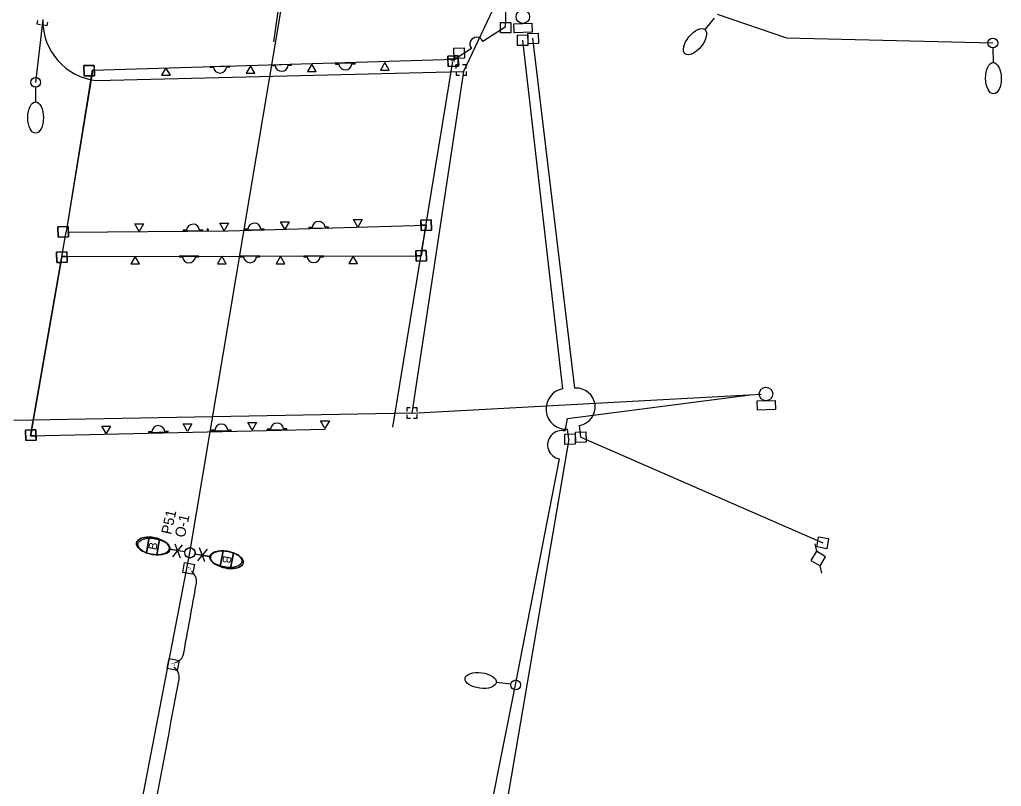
# Model space of a CAD drawing. Extents: x 925407 to 930994, y 604905 to 637063.
# Drawn here: x 930469.3 to 930944.1, y 618416 to 618786.5 of the extents above; entities that cross this region are included whole.
import ezdxf

# ---------------------------------------------------------------- set-up
doc = ezdxf.new("R2010")
doc.units = 0
for name, color, linetype in [('ActivePointCell_dp', 7, 'Continuous'), ('Conduit', 7, 'Continuous'), ('ConduitDB', 7, 'Continuous'), ('ConduitJB', 7, 'Continuous'), ('ConduitOT', 7, 'Continuous'), ('LightingMisc', 7, 'Continuous'), ('LiteCond_ep', 7, 'Continuous'), ('LoadCenter', 7, 'Continuous'), ('LoadCenter_ep', 7, 'Continuous'), ('Miscellaneous2', 7, 'Continuous'), ('Miscellaneous9', 7, 'Continuous'), ('PoleElec_ep', 7, 'Continuous'), ('PoleLight', 7, 'Continuous'), ('PoleLight_ep', 7, 'Continuous'), ('PullBox', 7, 'Continuous'), ('SoilBoxes_px', 7, 'Continuous')]:
    doc.layers.add(name, color=color, linetype=linetype)

msp = doc.modelspace()

# ---------------------------------------------------------------- linework, layer by layer
for points in [[(930560.46, 618685.29), (930560.02, 618685.33), (930559.93, 618684.52), (930560.37, 618684.47)], [(930560.37, 618684.47), (930560.46, 618685.29), (930560.46, 618685.29), (930560.37, 618684.47)]]:
    msp.add_lwpolyline(points, close=True)
at = {"layer": 'ActivePointCell_dp'}
msp.add_line((930618.39, 618963.87), (930592.1, 618775.67), dxfattribs=at)
at = {"layer": 'Conduit'}
for p, q in [((930720.15, 618838.16), (930683.96, 618761.37)), ((930806.63, 618789.06), (930840.21, 618777.66)), ((930480.53, 618786.47), (930477.05, 618756.15)), ((930840.21, 618777.66), (930939.95, 618775.21)), ((930506.57, 618757.04), (930683.96, 618761.37)), ((930683.96, 618761.37), (930659.01, 618596.36)), ((930659.01, 618596.36), (930827.84, 618605.52)), ((930734.26, 618593.79), (930822.57, 618605.19)), ((930659.01, 618596.36), (930466.5, 618592.68)), ((930733.07, 618587.68), (930734.26, 618593.79)), ((930709.17, 618464.99), (930730.45, 618574.22)), ((930671.82, 618277.75), (930709.17, 618464.96))]:
    msp.add_line(p, q, dxfattribs=at)
for centre, radius, start, end in [((930509.6, 618785.96), 29.08, 178.9945, 264.0152), ((930731.51, 618581), 6.87, 76.85, 261.1041)]:
    msp.add_arc(centre, radius, start, end, dxfattribs=at)
at = {"layer": 'ConduitDB'}
for p, q in [((930732.07, 618608.04), (930712.58, 618776.48)), ((930737.86, 618608.37), (930717.5, 618777.55)), ((930740.7, 618584.75), (930740.03, 618590.39)), ((930734.88, 618583.7), (930734.32, 618588.54)), ((930740.7, 618584.75), (930857.66, 618533.69))]:
    msp.add_line(p, q, dxfattribs=at)
for centre, radius, start, end in [((930733.68, 618598.35), 9.83, 99.4413, 273.7548), ((930738.6, 618599.34), 9.06, 279.0871, 94.6401)]:
    msp.add_arc(centre, radius, start, end, dxfattribs=at)
at = {"layer": 'ConduitJB'}
for p, q in [((930504.59, 618762.1), (930679.89, 618767.39)), ((930679.64, 618767.67), (930680.88, 618767.71)), ((930492.01, 618683.91), (930504.59, 618762.1)), ((930492.54, 618683.83), (930570.06, 618684.49)), ((930570.13, 618684.45), (930665.97, 618687.21)), ((930663.56, 618672.32), (930665.97, 618687.21)), ((930489.8, 618672), (930474.65, 618585.35)), ((930489.8, 618672), (930663.56, 618672.32)), ((930474.65, 618585.35), (930617, 618588.64))]:
    msp.add_line(p, q, dxfattribs=at)
at = {"layer": 'ConduitOT'}
for p, q in [((930704.72, 618801.33), (930704.15, 618782.79)), ((930704.15, 618782.79), (930693.37, 618775.96)), ((930687.86, 618772.46), (930679.94, 618767.43))]:
    msp.add_line(p, q, dxfattribs=at)
msp.add_lwpolyline([(930734.88, 618583.7), (930694.71, 618348.94)], dxfattribs=at)
for centre, radius, start, end in [((930690.34, 618774.64), 3.3, 23.4064, 221.404), ((930549.39, 618515.13), 5.5, 349.5299, 57.2394), ((919236.07, 620547.92), 11500, 349.639964, 349.813549), ((930543.25, 618481.17), 5.5, 281.9557, 349.5925), ((930540.98, 618468.82), 5.5, 349.5299, 57.2394), ((919236.07, 620547.92), 11500, 348.486539, 349.579184)]:
    msp.add_arc(centre, radius, start, end, dxfattribs=at)
at = {"layer": 'LightingMisc'}
for p, q in [((930600.75, 618764.81), (930591.23, 618764.54)), ((930591.23, 618764.54), (930591.24, 618764.22)), ((930599.15, 618764.44), (930600.76, 618764.49)), ((930600.76, 618764.49), (930600.75, 618764.81)), ((930631.62, 618765.42), (930622.1, 618765.25)), ((930622.1, 618765.25), (930622.1, 618764.93)), ((930622.1, 618764.93), (930623.71, 618764.96)), ((930630.02, 618765.07), (930631.62, 618765.1)), ((930631.62, 618765.1), (930631.62, 618765.42)), ((930570.94, 618763.93), (930561.42, 618763.72)), ((930561.42, 618763.72), (930561.43, 618763.41)), ((930561.43, 618763.41), (930563.03, 618763.44)), ((930569.34, 618763.58), (930570.95, 618763.62)), ((930570.95, 618763.62), (930570.94, 618763.93)), ((930591.24, 618764.22), (930592.84, 618764.27)), ((930550.03, 618684.73), (930548.43, 618684.72)), ((930548.43, 618684.72), (930548.43, 618684.4)), ((930548.43, 618684.4), (930557.95, 618684.48)), ((930557.95, 618684.8), (930556.35, 618684.79)), ((930557.95, 618684.48), (930557.95, 618684.8)), ((930579.69, 618685.21), (930578.09, 618685.19)), ((930578.09, 618685.19), (930578.09, 618684.87)), ((930578.09, 618684.87), (930587.61, 618684.96)), ((930587.61, 618685.27), (930586.01, 618685.26)), ((930587.61, 618684.96), (930587.61, 618685.27)), ((930610.71, 618686.06), (930609.11, 618686.05)), ((930609.11, 618686.05), (930609.11, 618685.73)), ((930609.11, 618685.73), (930618.63, 618685.81)), ((930618.63, 618686.13), (930617.03, 618686.12)), ((930618.63, 618685.81), (930618.63, 618686.13)), ((930555.92, 618672.12), (930546.4, 618672.11)), ((930546.4, 618672.11), (930546.4, 618671.79)), ((930546.4, 618671.79), (930548, 618671.79)), ((930554.32, 618671.8), (930555.92, 618671.81)), ((930555.92, 618671.81), (930555.92, 618672.12)), ((930585.51, 618672.18), (930575.99, 618672.16)), ((930575.99, 618672.16), (930575.99, 618671.85)), ((930575.99, 618671.85), (930577.6, 618671.85)), ((930583.91, 618671.86), (930585.51, 618671.86)), ((930585.51, 618671.86), (930585.51, 618672.18)), ((930616.28, 618672.23), (930606.76, 618672.22)), ((930606.76, 618672.22), (930606.76, 618671.9)), ((930606.76, 618671.9), (930608.36, 618671.9)), ((930614.68, 618671.91), (930616.28, 618671.92)), ((930616.28, 618671.92), (930616.28, 618672.23)), ((930598.6, 618588.79), (930597, 618588.75)), ((930598.61, 618588.47), (930598.6, 618588.79)), ((930533.19, 618587.35), (930531.58, 618587.31)), ((930531.58, 618587.31), (930531.59, 618586.99)), ((930531.59, 618586.99), (930541.11, 618587.21)), ((930541.1, 618587.53), (930539.5, 618587.49)), ((930541.11, 618587.21), (930541.1, 618587.53)), ((930563.7, 618588.11), (930562.1, 618588.1)), ((930562.1, 618588.1), (930562.1, 618587.78)), ((930562.1, 618587.78), (930571.62, 618587.84)), ((930571.62, 618588.15), (930570.01, 618588.14)), ((930571.62, 618587.84), (930571.62, 618588.15)), ((930590.69, 618588.62), (930589.08, 618588.58)), ((930589.08, 618588.58), (930589.09, 618588.26)), ((930589.09, 618588.26), (930598.61, 618588.47))]:
    msp.add_line(p, q, dxfattribs=at)
for points in [[(930608.56, 618761.33), (930612.78, 618761.33), (930610.67, 618764.99)], [(930643.82, 618762.06), (930648.04, 618762.06), (930645.93, 618765.72)], [(930537.99, 618759.56), (930542.21, 618759.56), (930540.1, 618763.21)], [(930578.83, 618760.56), (930583.05, 618760.56), (930580.94, 618764.22)], [(930595.47, 618688.84), (930599.68, 618688.84), (930597.58, 618685.19)], [(930630.77, 618689.86), (930634.99, 618689.86), (930632.88, 618686.2)], [(930525, 618687.72), (930529.22, 618687.72), (930527.11, 618684.07)], [(930566.09, 618688.07), (930570.31, 618688.07), (930568.2, 618684.42)], [(930523.08, 618668.42), (930527.3, 618668.42), (930525.19, 618672.08)], [(930564.97, 618668.54), (930569.19, 618668.54), (930567.08, 618672.19)], [(930593.38, 618668.52), (930597.6, 618668.52), (930595.49, 618672.17)], [(930628.53, 618668.58), (930632.75, 618668.58), (930630.64, 618672.24)], [(930509.05, 618590.08), (930513.27, 618590.08), (930511.16, 618586.43)], [(930548.44, 618591.08), (930552.66, 618591.08), (930550.55, 618587.42)], [(930579.61, 618591.75), (930583.83, 618591.75), (930581.72, 618588.09)], [(930614.88, 618592.56), (930619.1, 618592.56), (930616.99, 618588.91)]]:
    msp.add_lwpolyline(points, close=True, dxfattribs=at)
for centre, start, end in [((930595.99, 618764.67), 187.3392, 355.8608), ((930626.86, 618765.33), 186.7733, 355.2948), ((930566.18, 618763.83), 186.9974, 355.519), ((930613.87, 618685.77), 6.2311, 174.7527), ((930553.19, 618684.44), 6.2264, 174.748), ((930582.85, 618684.92), 6.2264, 174.748), ((930551.16, 618672.12), 185.8184, 354.34), ((930580.75, 618672.17), 185.8184, 354.34), ((930611.52, 618672.23), 185.8184, 354.34), ((930536.35, 618587.1), 7.061, 175.5826), ((930566.86, 618587.81), 6.0485, 174.5701), ((930593.85, 618588.37), 6.9778, 175.4994)]:
    msp.add_arc(centre, 3.17, start, end, dxfattribs=at)
at = {"layer": 'LiteCond_ep'}
for p, q in [((930551.66, 618528.87), (930598.48, 618807.43)), ((930505.44, 618764.38), (930500.44, 618764.25)), ((930505.5, 618762.12), (930505.44, 618764.38)), ((930679.57, 618768.98), (930676.35, 618768.9)), ((930676.35, 618768.9), (930676.39, 618767.29)), ((930676.39, 618767.29), (930679.48, 618767.38)), ((930676.39, 618767.29), (930676.48, 618763.9)), ((930679.64, 618767.67), (930679.48, 618767.38)), ((930679.48, 618767.38), (930679.65, 618767.39)), ((930679.48, 618767.38), (930679.89, 618767.39)), ((930681.35, 618769.02), (930679.57, 618768.98)), ((930681.35, 618769.02), (930679.57, 618768.98)), ((930679.64, 618767.67), (930679.57, 618768.98)), ((930679.57, 618768.98), (930679.64, 618767.67)), ((930679.83, 618767.71), (930679.57, 618768.98)), ((930679.83, 618767.68), (930679.64, 618767.67)), ((930679.64, 618767.67), (930679.83, 618767.68)), ((930679.83, 618767.68), (930679.83, 618767.71)), ((930679.84, 618767.66), (930679.83, 618767.68)), ((930680.33, 618767.67), (930679.84, 618767.66)), ((930680.8, 618767.68), (930679.89, 618767.39)), ((930679.89, 618767.39), (930680.33, 618767.67)), ((930680.33, 618767.67), (930679.89, 618767.39)), ((930679.89, 618767.39), (930680.37, 618767.55)), ((930680.3, 618764.61), (930681.46, 618764.62)), ((930681.46, 618764.62), (930680.3, 618764.61)), ((930680.3, 618764), (930680.3, 618764.61)), ((930680.3, 618764.61), (930680.3, 618764)), ((930680.72, 618767.7), (930680.33, 618767.67)), ((930680.33, 618767.67), (930680.72, 618767.7)), ((930680.36, 618767.69), (930680.33, 618767.67)), ((930680.73, 618767.93), (930680.36, 618767.69)), ((930680.73, 618767.93), (930680.36, 618767.69)), ((930680.36, 618767.69), (930680.88, 618767.71)), ((930680.88, 618767.71), (930680.36, 618767.69)), ((930680.36, 618767.69), (930680.72, 618767.7)), ((930680.72, 618767.7), (930680.36, 618767.69)), ((930680.36, 618767.69), (930680.72, 618767.7)), ((930680.36, 618767.69), (930680.36, 618767.69)), ((930680.37, 618767.55), (930680.8, 618767.68)), ((930680.72, 618767.7), (930680.88, 618767.71)), ((930680.72, 618767.7), (930680.85, 618767.71)), ((930680.85, 618767.71), (930680.72, 618767.7)), ((930680.8, 618767.7), (930680.72, 618767.7)), ((930681.37, 618768.33), (930680.73, 618767.93)), ((930681.37, 618768.33), (930680.73, 618767.93)), ((930680.8, 618767.68), (930681.39, 618767.7)), ((930680.85, 618767.7), (930680.8, 618767.68)), ((930680.8, 618767.68), (930680.85, 618767.7)), ((930680.85, 618767.7), (930680.8, 618767.7)), ((930680.85, 618767.71), (930680.88, 618767.71)), ((930680.88, 618767.71), (930681.06, 618767.7)), ((930680.88, 618767.71), (930681.06, 618767.7)), ((930681.06, 618767.7), (930681.38, 618767.71)), ((930681.39, 618767.7), (930681.06, 618767.7)), ((930681.06, 618767.7), (930681.39, 618767.7)), ((930681.37, 618768.33), (930681.35, 618769.02)), ((930681.37, 618768.33), (930681.35, 618769.02)), ((930681.38, 618767.71), (930681.37, 618768.33)), ((930681.39, 618767.7), (930681.37, 618768.33)), ((930681.46, 618764.62), (930681.39, 618767.7)), ((930681.48, 618764.1), (930681.46, 618764.62)), ((930500.44, 618764.25), (930500.57, 618759.25)), ((930504.15, 618759.34), (930504.59, 618762.1)), ((930504.59, 618762.1), (930504.15, 618759.34)), ((930504.59, 618762.1), (930505.5, 618762.12)), ((930505.5, 618762.12), (930504.59, 618762.1)), ((930505.57, 618759.38), (930505.5, 618762.12)), ((930676.48, 618763.9), (930680.3, 618764)), ((930680.3, 618764), (930681.41, 618764.02)), ((930500.57, 618759.25), (930504.15, 618759.34)), ((930504.15, 618759.34), (930505.57, 618759.38)), ((930668.4, 618689.77), (930663.4, 618689.64)), ((930663.4, 618689.64), (930663.47, 618687.14)), ((930668.53, 618684.77), (930668.4, 618689.77)), ((930487.84, 618686.33), (930487.97, 618681.33)), ((930665.97, 618687.21), (930663.47, 618687.14)), ((930663.47, 618687.14), (930665.97, 618687.21)), ((930663.47, 618687.14), (930663.53, 618684.65)), ((930663.53, 618684.65), (930665.56, 618684.7)), ((930665.56, 618684.7), (930665.97, 618687.21)), ((930665.97, 618687.21), (930665.56, 618684.7)), ((930665.56, 618684.7), (930668.53, 618684.77)), ((930487.97, 618681.33), (930492.97, 618681.46)), ((930492.18, 618674.25), (930487.18, 618674.12)), ((930487.18, 618674.12), (930487.31, 618669.13)), ((930492.24, 618672.01), (930492.18, 618674.25)), ((930663.96, 618674.84), (930660.99, 618674.76)), ((930660.99, 618674.76), (930661.06, 618672.32)), ((930663.96, 618674.84), (930663.56, 618672.32)), ((930663.56, 618672.32), (930663.96, 618674.84)), ((930665.99, 618674.89), (930663.96, 618674.84)), ((930666.12, 618669.89), (930665.99, 618674.89)), ((930489.31, 618669.18), (930489.8, 618672)), ((930489.8, 618672), (930489.31, 618669.18)), ((930489.8, 618672), (930492.24, 618672.01)), ((930492.24, 618672.01), (930489.8, 618672)), ((930492.31, 618669.25), (930492.24, 618672.01)), ((930663.56, 618672.32), (930661.06, 618672.32)), ((930661.06, 618672.32), (930661.12, 618669.76)), ((930661.06, 618672.32), (930663.56, 618672.32)), ((930661.12, 618669.76), (930666.12, 618669.89)), ((930487.31, 618669.13), (930489.31, 618669.18)), ((930489.31, 618669.18), (930492.31, 618669.25)), ((930475.15, 618588.19), (930472.14, 618588.11)), ((930472.14, 618588.11), (930472.27, 618583.11)), ((930474.65, 618585.35), (930475.15, 618588.19)), ((930475.15, 618588.19), (930474.65, 618585.35)), ((930477.21, 618585.41), (930474.65, 618585.35)), ((930474.65, 618585.35), (930477.21, 618585.41)), ((930477.14, 618588.24), (930475.15, 618588.19)), ((930477.21, 618585.41), (930477.14, 618588.24)), ((930477.27, 618583.24), (930477.21, 618585.41)), ((930472.27, 618583.11), (930477.27, 618583.24)), ((930498.32, 618253.03), (930551.66, 618528.87))]:
    msp.add_line(p, q, dxfattribs=at)
for points in [[(930679.89, 618767.39), (930679.48, 618767.38), (930676.39, 618767.29)], [(930679.57, 618768.98), (930679.82, 618767.72), (930679.84, 618767.66)], [(930679.57, 618768.98), (930679.83, 618767.71), (930679.83, 618767.68)], [(930679.64, 618767.67), (930679.83, 618767.71)], [(930679.83, 618767.71), (930679.64, 618767.67)], [(930679.65, 618767.39), (930679.64, 618767.67)], [(930679.83, 618767.68), (930679.84, 618767.68), (930680.33, 618767.69), (930680.36, 618767.69)], [(930679.84, 618767.66), (930679.89, 618767.66), (930680.33, 618767.67)], [(930680.33, 618767.67), (930680.73, 618767.93), (930681.37, 618768.33)], [(930680.37, 618767.55), (930680.33, 618767.67)], [(930680.33, 618767.67), (930680.37, 618767.55)], [(930680.36, 618767.69), (930680.73, 618767.93), (930681.37, 618768.33)], [(930680.72, 618767.7), (930680.8, 618767.7), (930680.85, 618767.7)], [(930681.39, 618767.7), (930680.88, 618767.69), (930680.8, 618767.68)], [(930680.8, 618767.68), (930680.8, 618767.7)], [(930680.8, 618767.7), (930680.8, 618767.68)], [(930680.85, 618767.7), (930680.85, 618767.71)], [(930681.06, 618767.7), (930680.88, 618767.7), (930680.85, 618767.7)], [(930681.41, 618764.02), (930681.44, 618764.06), (930681.48, 618764.1)], [(930492.84, 618686.46), (930492.42, 618686.45), (930487.84, 618686.33)], [(930492.97, 618681.46), (930492.91, 618683.83), (930492.84, 618686.46)]]:
    msp.add_lwpolyline(points, dxfattribs=at)
at = {"layer": 'LoadCenter'}
for p, q in [((930708.36, 618784.5), (930717.09, 618784.73)), ((930708.47, 618780.14), (930708.36, 618784.5)), ((930717.09, 618784.73), (930717.2, 618780.36)), ((930717.2, 618780.36), (930708.47, 618780.14))]:
    msp.add_line(p, q, dxfattribs=at)
msp.add_circle((930712.64, 618787.89), 3.27, dxfattribs=at)
at = {"layer": 'LoadCenter_ep'}
for p, q in [((930825.97, 618602.19), (930834.69, 618602.42)), ((930826.08, 618597.83), (930825.97, 618602.19)), ((930834.69, 618602.42), (930834.8, 618598.05)), ((930834.8, 618598.05), (930826.08, 618597.83))]:
    msp.add_line(p, q, dxfattribs=at)
msp.add_circle((930830.24, 618605.58), 3.27, dxfattribs=at)
at = {"layer": 'Miscellaneous2'}
for p, q in [((930532, 618536.38), (930530.59, 618528.85)), ((930532, 618536.38), (930532, 618536.38)), ((930535.6, 618527.91), (930537.01, 618535.44)), ((930537.01, 618535.44), (930537.01, 618535.44)), ((930567.73, 618529.7), (930566.32, 618522.16)), ((930567.73, 618529.7), (930567.73, 618529.7)), ((930571.33, 618521.22), (930572.74, 618528.76)), ((930572.74, 618528.76), (930572.74, 618528.76))]:
    msp.add_line(p, q, dxfattribs=at)
for centre, start_param, end_param in [((930533.8, 618532.15), 1.249648, 1.891946), ((930533.8, 618532.15), 4.391241, 4.391271), ((930533.8, 618532.15), 4.391271, 5.033538), ((930569.53, 618525.46), 1.249648, 1.891946), ((930569.53, 618525.46), 4.391241, 4.391271), ((930569.53, 618525.46), 4.391271, 5.033538)]:
    msp.add_ellipse(centre, major_axis=(7.94, -1.49), ratio=0.5, start_param=start_param, end_param=end_param, dxfattribs=at)
at = {"layer": 'PoleElec_ep'}
for p, q in [((930853.82, 618533.08), (930854.68, 618529.54)), ((930857.24, 618518.98), (930856.38, 618522.52))]:
    msp.add_line(p, q, dxfattribs=at)
msp.add_lwpolyline([(930854.68, 618529.54), (930852.01, 618525.18), (930856.38, 618522.52), (930859.04, 618526.88), (930854.68, 618529.54)], dxfattribs=at)
at = {"layer": 'PoleLight'}
for p, q in [((930530.59, 618528.85), (930532, 618536.38)), ((930537.01, 618535.44), (930535.6, 618527.91)), ((930549.18, 618529.27), (930541.74, 618530.66)), ((930554.15, 618528.34), (930561.59, 618526.95)), ((930566.32, 618522.16), (930567.73, 618529.7)), ((930572.74, 618528.76), (930571.33, 618521.22))]:
    msp.add_line(p, q, dxfattribs=at)
msp.add_circle((930551.67, 618528.8), 2.52, dxfattribs=at)
msp.add_circle((930551.67, 618528.8), 2.52, dxfattribs=at)
for centre in [(930533.8, 618532.15), (930569.53, 618525.46)]:
    msp.add_ellipse(centre, major_axis=(7.94, -1.49), ratio=0.5, dxfattribs=at)
for centre, start_param, end_param in [((930533.8, 618532.15), 1.891945, 4.391241), ((930533.8, 618532.15), 0.847605, 1.249648), ((930533.8, 618532.15), 0, 0.847605), ((930533.8, 618532.15), 5.033538, 6.283185), ((930569.53, 618525.46), 1.891945, 4.391241), ((930569.53, 618525.46), 0.847605, 1.249648), ((930569.53, 618525.46), 0, 0.847605), ((930569.53, 618525.46), 5.033538, 6.283185)]:
    msp.add_ellipse(centre, major_axis=(7.94, -1.49), ratio=0.5, start_param=start_param, end_param=end_param, dxfattribs=at)
at = {"layer": 'PoleLight_ep'}
for p, q in [((930805.14, 618787.21), (930800.68, 618781.69)), ((930939.98, 618772.84), (930940.1, 618765.74)), ((930477.05, 618753.78), (930477.05, 618746.69)), ((930543.35, 618526.95), (930548.04, 618532.61)), ((930544.42, 618533.23), (930546.97, 618526.33)), ((930549.25, 618529.22), (930542, 618530.45)), ((930554.08, 618528.39), (930561.33, 618527.16)), ((930559.98, 618530.65), (930555.29, 618525)), ((930558.91, 618524.38), (930556.36, 618531.27)), ((930706.82, 618465.29), (930699.78, 618466.18))]:
    msp.add_line(p, q, dxfattribs=at)
for centre, radius in [((930939.95, 618775.21), 2.37), ((930477.05, 618756.15), 2.37), ((930551.67, 618528.8), 2.45), ((930709.17, 618464.99), 2.37)]:
    msp.add_circle(centre, radius, dxfattribs=at)
for centre, major_axis in [((930795.93, 618775.8), (-4.75, -5.89)), ((930940.22, 618758.17), (0.12, -7.57)), ((930477.04, 618739.12), (0, -7.57)), ((930534.28, 618531.77), (-7.73, 1.32)), ((930569.05, 618525.84), (7.73, -1.32)), ((930692.27, 618467.14), (-7.51, 0.96))]:
    msp.add_ellipse(centre, major_axis=major_axis, ratio=0.5, dxfattribs=at)
at = {"layer": 'PullBox'}
for p, q in [((930701.79, 618785.03), (930706.79, 618785.16)), ((930701.92, 618780.03), (930701.79, 618785.03)), ((930706.79, 618785.16), (930706.92, 618780.16)), ((930706.92, 618780.16), (930701.92, 618780.03)), ((930710.02, 618778.92), (930715.02, 618779.05)), ((930710.15, 618773.92), (930710.02, 618778.92)), ((930715.02, 618779.05), (930715.15, 618774.05)), ((930715.14, 618779.78), (930720.14, 618779.91)), ((930715.27, 618774.79), (930715.14, 618779.78)), ((930720.14, 618779.91), (930720.27, 618774.91)), ((930715.15, 618774.05), (930710.15, 618773.92)), ((930720.27, 618774.91), (930715.27, 618774.79)), ((930679.34, 618772.65), (930684.34, 618772.78)), ((930679.47, 618767.65), (930679.34, 618772.65)), ((930684.34, 618772.78), (930684.47, 618767.78)), ((930500.44, 618764.25), (930505.44, 618764.38)), ((930505.44, 618764.38), (930505.57, 618759.38)), ((930676.35, 618768.9), (930681.35, 618769.02)), ((930676.48, 618763.9), (930676.35, 618768.9)), ((930684.47, 618767.78), (930679.47, 618767.65)), ((930681.35, 618769.02), (930681.48, 618764.03)), ((930500.57, 618759.25), (930500.44, 618764.25)), ((930681.48, 618764.03), (930676.48, 618763.9)), ((930505.57, 618759.38), (930500.57, 618759.25)), ((930663.4, 618689.64), (930668.4, 618689.77)), ((930663.53, 618684.65), (930663.4, 618689.64)), ((930668.4, 618689.77), (930668.53, 618684.77)), ((930487.84, 618686.33), (930492.84, 618686.46)), ((930487.97, 618681.33), (930487.84, 618686.33)), ((930492.84, 618686.46), (930492.97, 618681.46)), ((930668.53, 618684.77), (930663.53, 618684.65)), ((930492.97, 618681.46), (930487.97, 618681.33)), ((930487.18, 618674.12), (930492.18, 618674.25)), ((930487.31, 618669.13), (930487.18, 618674.12)), ((930492.18, 618674.25), (930492.31, 618669.25)), ((930660.99, 618674.76), (930665.99, 618674.89)), ((930661.12, 618669.76), (930660.99, 618674.76)), ((930665.99, 618674.89), (930666.12, 618669.89)), ((930666.12, 618669.89), (930661.12, 618669.76)), ((930492.31, 618669.25), (930487.31, 618669.13)), ((930472.14, 618588.11), (930477.14, 618588.24)), ((930472.27, 618583.11), (930472.14, 618588.11)), ((930477.14, 618588.24), (930477.27, 618583.24)), ((930732.9, 618586.16), (930737.9, 618586.29)), ((930733.03, 618581.16), (930732.9, 618586.16)), ((930737.9, 618586.29), (930738.03, 618581.29)), ((930738.14, 618587.19), (930743.14, 618587.32)), ((930738.27, 618582.19), (930738.14, 618587.19)), ((930743.14, 618587.32), (930743.27, 618582.32)), ((930477.27, 618583.24), (930472.27, 618583.11)), ((930738.03, 618581.29), (930733.03, 618581.16)), ((930743.27, 618582.32), (930738.27, 618582.19)), ((930854.78, 618531.63), (930855.6, 618536.57)), ((930855.6, 618536.57), (930860.53, 618535.75)), ((930860.53, 618535.75), (930859.71, 618530.82)), ((930859.71, 618530.82), (930854.78, 618531.63)), ((930548.17, 618519.35), (930549.06, 618524.11)), ((930549.06, 618524.11), (930553.82, 618523.22)), ((930553.82, 618523.22), (930552.93, 618518.46)), ((930552.93, 618518.46), (930548.17, 618519.35)), ((930540.73, 618472.9), (930541.62, 618477.67)), ((930541.62, 618477.67), (930546.39, 618476.78)), ((930546.39, 618476.78), (930545.5, 618472.01)), ((930545.5, 618472.01), (930540.73, 618472.9))]:
    msp.add_line(p, q, dxfattribs=at)
for points in [[(930477.99, 618786.12), (930477.7, 618784.41), (930479.36, 618784.14)], [(930480.89, 618783.89), (930482.64, 618783.6)], [(930482.64, 618783.6), (930482.92, 618785.31)], [(930681.97, 618764.63), (930680.3, 618764.61), (930680.32, 618762.85)], [(930685.32, 618762.91), (930685.3, 618764.67), (930683.52, 618764.65)], [(930680.34, 618761.35), (930680.36, 618759.61), (930682.04, 618759.64)], [(930683.59, 618759.66), (930685.36, 618759.68)], [(930685.36, 618759.68), (930685.34, 618761.41)], [(930658.18, 618598.85), (930656.5, 618598.82), (930656.54, 618597.05)], [(930661.54, 618597.16), (930661.5, 618598.92), (930659.73, 618598.89)], [(930656.57, 618595.55), (930656.61, 618593.82), (930658.29, 618593.86)], [(930659.84, 618593.89), (930661.61, 618593.93)], [(930661.61, 618593.93), (930661.57, 618595.66)]]:
    msp.add_lwpolyline(points, dxfattribs=at)
at = {"layer": 'SoilBoxes_px'}
for p, q in [((930678.7, 618766.31), (930649.59, 618589.52)), ((930678.7, 618766.31), (930649.59, 618589.52)), ((930491.97, 618683.92), (930504.8, 618762.38)), ((930474.63, 618585.36), (930491.8, 618683.91))]:
    msp.add_line(p, q, dxfattribs=at)

# ---------------------------------------------------------------- texts
at = {"layer": 'ActivePointCell_dp'}
for s, p in [('P51', (930542.6, 618537.36)), ('O-1', (930549.14, 618535.91))]:
    msp.add_text(s, height=5, rotation=77.5026, dxfattribs=at).set_placement(p)
at = {"layer": 'Miscellaneous9'}
for rotation, p in [(79.4013, (930535.46, 618529.94)), (259.4013, (930567.87, 618527.67))]:
    msp.add_text('B', height=4.08, rotation=rotation, dxfattribs=at).set_placement(p)
at = {"layer": 'PullBox'}
for height, rotation, p in [(2, 91.4756, (930679.93, 618765.81)), (1.94, 79.4065, (930551.83, 618520.46)), (1.94, 79.4065, (930544.39, 618474.02))]:
    msp.add_text('J', height=height, rotation=rotation, dxfattribs=at).set_placement(p)

doc.saveas('drawing.dxf')
